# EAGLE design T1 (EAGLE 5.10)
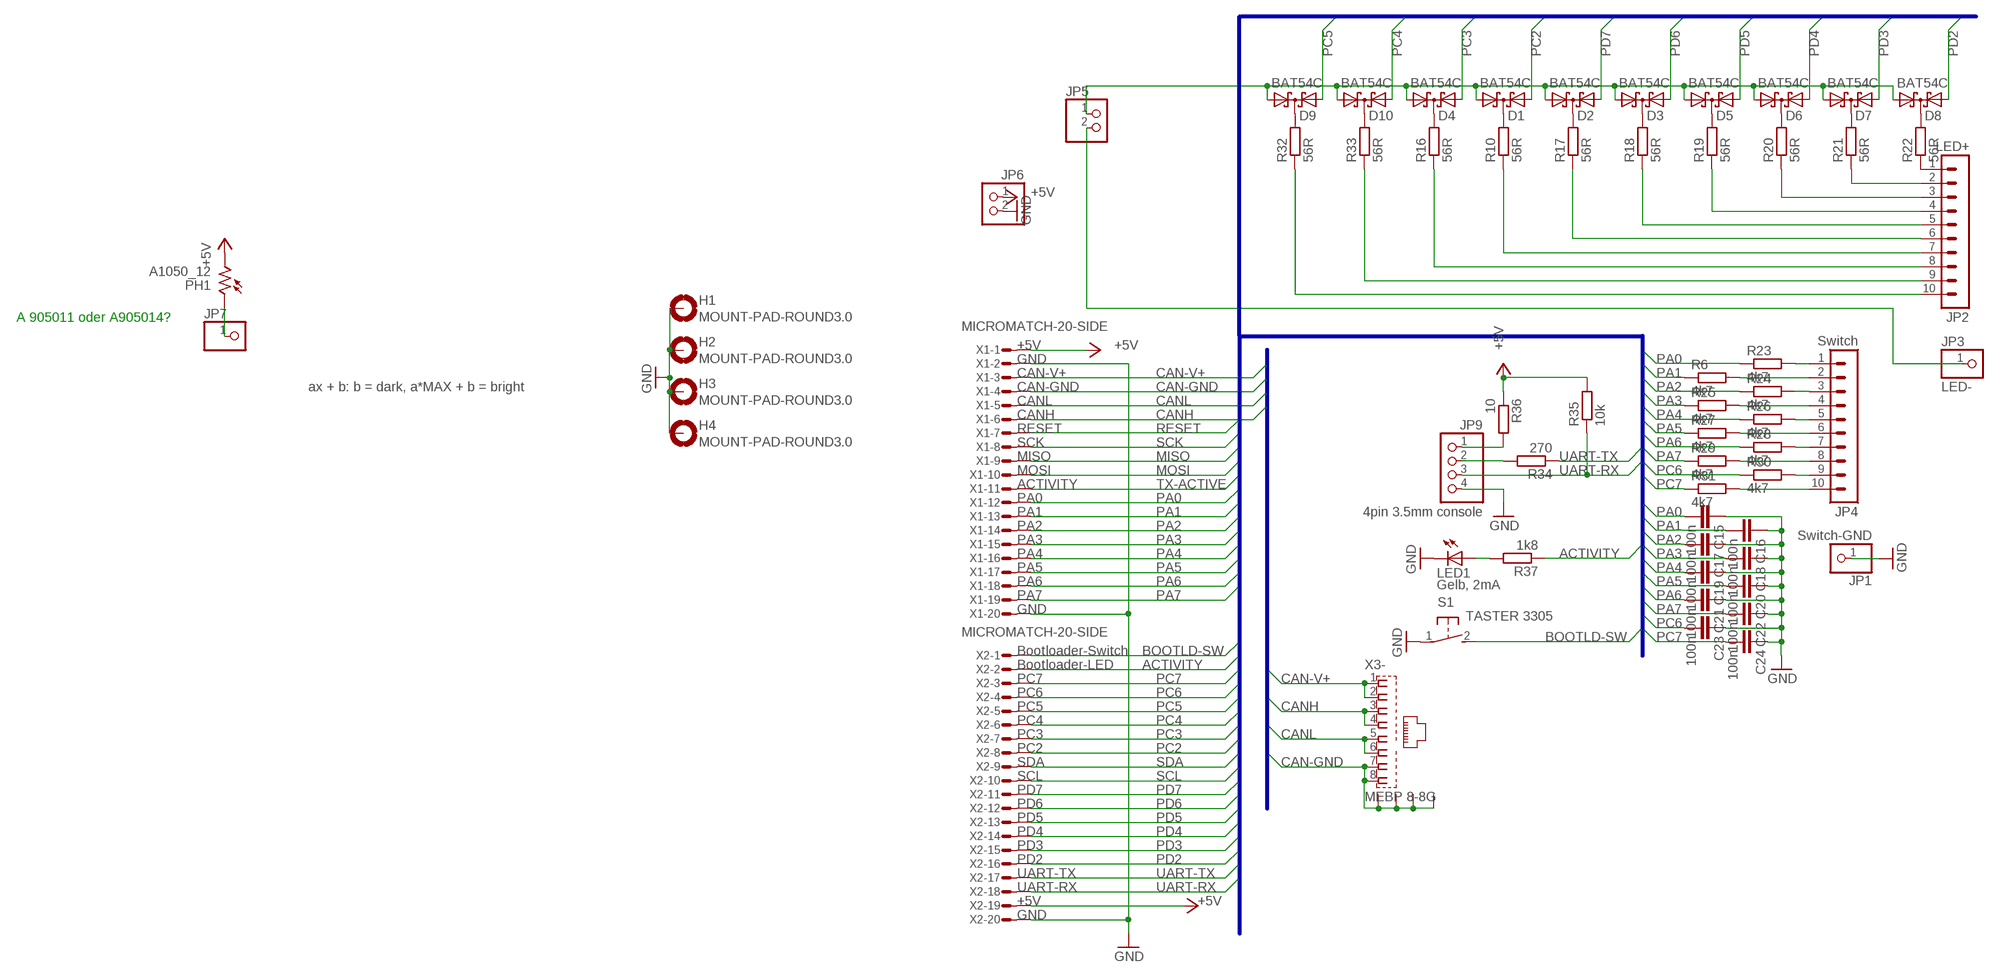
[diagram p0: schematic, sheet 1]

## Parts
C15  100n  C-EUC0805  [C0805]
C16  100n  C-EUC0805  [C0805]
C17  100n  C-EUC0805  [C0805]
C18  100n  C-EUC0805  [C0805]
C19  100n  C-EUC0805  [C0805]
C20  100n  C-EUC0805  [C0805]
C21  100n  C-EUC0805  [C0805]
C22  100n  C-EUC0805  [C0805]
C23  100n  C-EUC0805  [C0805]
C24  100n  C-EUC0805  [C0805]
D1  BAT54C  [SOT23]
D2  BAT54C  [SOT23]
D3  BAT54C  [SOT23]
D4  BAT54C  [SOT23]
D5  BAT54C  [SOT23]
D6  BAT54C  [SOT23]
D7  BAT54C  [SOT23]
D8  BAT54C  [SOT23]
D9  BAT54C  [SOT23]
D10  BAT54C  [SOT23]
H1  MOUNT-PAD-ROUND3.0  [3,0-PAD]
H2  MOUNT-PAD-ROUND3.0  [3,0-PAD]
H3  MOUNT-PAD-ROUND3.0  [3,0-PAD]
H4  MOUNT-PAD-ROUND3.0  [3,0-PAD]
JP1  Switch-GND  PINHD-1X1  [1X01]
JP2  LED+  MA10-1  [MA10-1]
JP3  LED-  PINHD-1X1  [1X01]
JP4  Switch  MA10-1  [MA10-1]
JP5  PINHD-1X2  [1X02]
JP6  PINHD-1X2  [1X02]
JP7  PINHD-1X1  [1X01]
JP9  4pin 3.5mm console  PINHD-1X4  [1X04]
LED1  Gelb, 2mA  LED3MM  [LED3MM]
PH1  A1050_12  [T0-46-A10XX]
R6  4k7  R-EU_0207/10  [0207/10]
R10  56R  R-EU_0207/10  [0207/10]
R16  56R  R-EU_0207/10  [0207/10]
R17  56R  R-EU_0207/10  [0207/10]
R18  56R  R-EU_0207/10  [0207/10]
R19  56R  R-EU_0207/10  [0207/10]
R20  56R  R-EU_0207/10  [0207/10]
R21  56R  R-EU_0207/10  [0207/10]
R22  56R  R-EU_0207/10  [0207/10]
R23  4k7  R-EU_0207/10  [0207/10]
R24  4k7  R-EU_0207/10  [0207/10]
R25  4k7  R-EU_0207/10  [0207/10]
R26  4k7  R-EU_0207/10  [0207/10]
R27  4k7  R-EU_0207/10  [0207/10]
R28  4k7  R-EU_0207/10  [0207/10]
R29  4k7  R-EU_0207/10  [0207/10]
R30  4k7  R-EU_0207/10  [0207/10]
R31  4k7  R-EU_0207/10  [0207/10]
R32  56R  R-EU_0207/10  [0207/10]
R33  56R  R-EU_0207/10  [0207/10]
R34  270  R-EU_R0805  [R0805]
R35  10k  R-EU_R0805  [R0805]
R36  10  R-EU_R0805  [R0805]
R37  1k8  R-EU_R0805  [R0805]
S1  TASTER 3305  31-XX  [B3F-31XX]
X1  MICROMATCH-20-SIDE  [MICROMATCH-20-SIDE]
X2  MICROMATCH-20-SIDE  [MICROMATCH-20-SIDE]
X3  MEBP 8-8G  RJ45  [RJ45]

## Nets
+5V: JP6.1 PH1.2 R35.2 R36.1 X1.1 X2.19
ACTIVITY: R37.1 X2.2
ACTIVITY_LED: LED1.A R37.2
BOOTLD-SW: S1.2(S) X2.1
CAN-GND [Power]: X1.4 X3.7 X3.8 X3.G1 X3.G2 X3.G3 X3.G4
CAN-V+ [Power]: X1.3 X3.1 X3.2
CANH: X1.6 X3.3 X3.4
CANL: X1.5 X3.5 X3.6
GND: C15.1 C16.1 C17.1 C18.1 C19.1 C20.1 C21.1 C22.1 C23.1 C24.1 H1.B3,0(MOUNT) H2.B3,0(MOUNT) H3.B3,0(MOUNT) H4.B3,0(MOUNT) JP1.1 JP6.2 JP9.4 LED1.K(C) S1.1(P) X1.2 X1.20 X2.20
MISO: X1.9
MOSI: X1.10
N$1: JP7.1 PH1.1
N$2: D4.3(CC) R16.2
N$14: JP4.1 R23.2
N$22: JP2.8 R16.1
N$23: D1.3(CC) R10.2
N$24: JP2.7 R10.1
N$25: JP4.3 R24.2
N$26: D2.3(CC) R17.2
N$27: JP2.6 R17.1
N$28: D3.3(CC) R18.2
N$29: JP2.5 R18.1
N$30: JP4.10 R31.2
N$31: D5.3(CC) R19.2
N$32: JP2.4 R19.1
N$33: D6.3(CC) R20.2
N$34: JP2.3 R20.1
N$35: JP4.2 R6.2
N$36: D7.3(CC) R21.2
N$37: JP2.2 R21.1
N$38: D8.3(CC) R22.2
N$39: JP2.1 R22.1
N$40: JP4.4 R25.2
N$41: JP4.5 R26.2
N$42: JP4.6 R27.2
N$43: JP4.7 R28.2
N$44: JP4.8 R29.2
N$45: JP4.9 R30.2
N$46: JP9.2 R34.2
N$47: JP9.1 R36.2
N$49: D9.3(CC) R32.2
N$50: JP2.10 R32.1
N$51: D10.3(CC) R33.2
N$52: JP2.9 R33.1
N$54: JP3.1 JP5.2
N$55: D1.1(A1) D2.1(A1) D3.1(A1) D4.1(A1) D5.1(A1) D6.1(A1) D7.1(A1) D8.1(A1) D9.1(A1) D10.1(A1) JP5.1
PA0: C15.2 R23.1 X1.12
PA1: C16.2 R6.1 X1.13
PA2: C17.2 R24.1 X1.14
PA3: C18.2 R25.1 X1.15
PA4: C19.2 R26.1 X1.16
PA5: C20.2 R27.1 X1.17
PA6: C21.2 R28.1 X1.18
PA7: C22.2 R29.1 X1.19
PC2: D1.2(A2) X2.8
PC3: D4.2(A2) X2.7
PC4: D10.2(A2) X2.6
PC5: D9.2(A2) X2.5
PC6: C23.2 R30.1 X2.4
PC7: C24.2 R31.1 X2.3
PD2: D8.2(A2) X2.16
PD3: D7.2(A2) X2.15
PD4: D6.2(A2) X2.14
PD5: D5.2(A2) X2.13
PD6: D3.2(A2) X2.12
PD7: D2.2(A2) X2.11
RESET: X1.7
SCK: X1.8
SCL: X2.10
SDA: X2.9
TX-ACTIVE: X1.11
UART-RX: JP9.3 R35.1 X2.18
UART-TX: R34.1 X2.17

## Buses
PA[0..7],PC[2..7],PD[2..7],SCK,MISO,MOSI,CAN-CS,BOOTLD-SW,CAN-INT,TX-ACTIVE,ACTIVITY,SDA,SCL,UART-RX,UART-TX,CLK,RESET
CANL,CANH,CAN-V+,CAN-GND

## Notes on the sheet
- A 905011 oder A905014?
- +5V
- GND
- CAN-V+
- ax + b: b = dark, a*MAX + b = bright | CAN-GND
- CANL
- CANH
- RESET
- SCK
- MISO
- MOSI
- ACTIVITY
- PA0
- PA1
- PA2
- PA3
- PA4
- PA5
- PA6
- PA7
- GND
- Bootloader-Switch
- Bootloader-LED
- PC7
- PC6
- PC5
- PC4
- PC3
- PC2
- SDA
- SCL
- PD7
- PD6
- PD5
- PD4
- PD3
- PD2
- UART-TX
- UART-RX
- +5V
- GND

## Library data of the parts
C15-C24 = rcl:C-EU: CAPACITOR, European symbol
D1-D10 = diode:BAT54C: Schottky Diodes Source: Fairchild .. BAT54.pdf
H1-H4 = holes:MOUNT-PAD-ROUND: MOUNTING PAD, round
JP1 JP3 JP7 = pinhead:PINHD-1X1: PIN HEADER
JP2 JP4 = con-lstb:MA10-1: PIN HEADER
JP5 JP6 = pinhead:PINHD-1X2: PIN HEADER
JP9 = pinhead:PINHD-1X4: PIN HEADER
LED1 = led:LED: LED
PH1 = photo-elements:A10: Sensor Robust Light Sensing Applications
R6 R10 R16-R37 = rcl:R-EU_: RESISTOR, European symbol
S1 = switch-omron:31-XX: OMRON SWITCH
X1 X2 = apbteam_con-amp-micromatch:MICROMATCH-20: Micro-MaTch 20 Straight connector: Suited for both, female and male.
X3 = con-appsys:RJ45: AMP connector

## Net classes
1 Power: width 0.5 mm

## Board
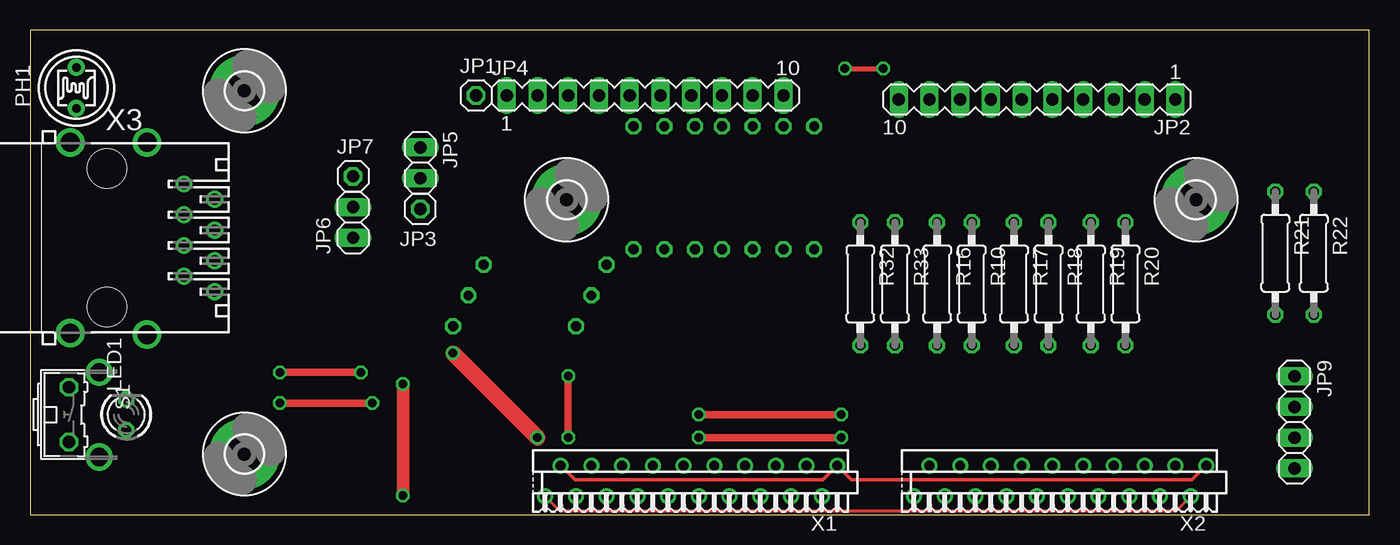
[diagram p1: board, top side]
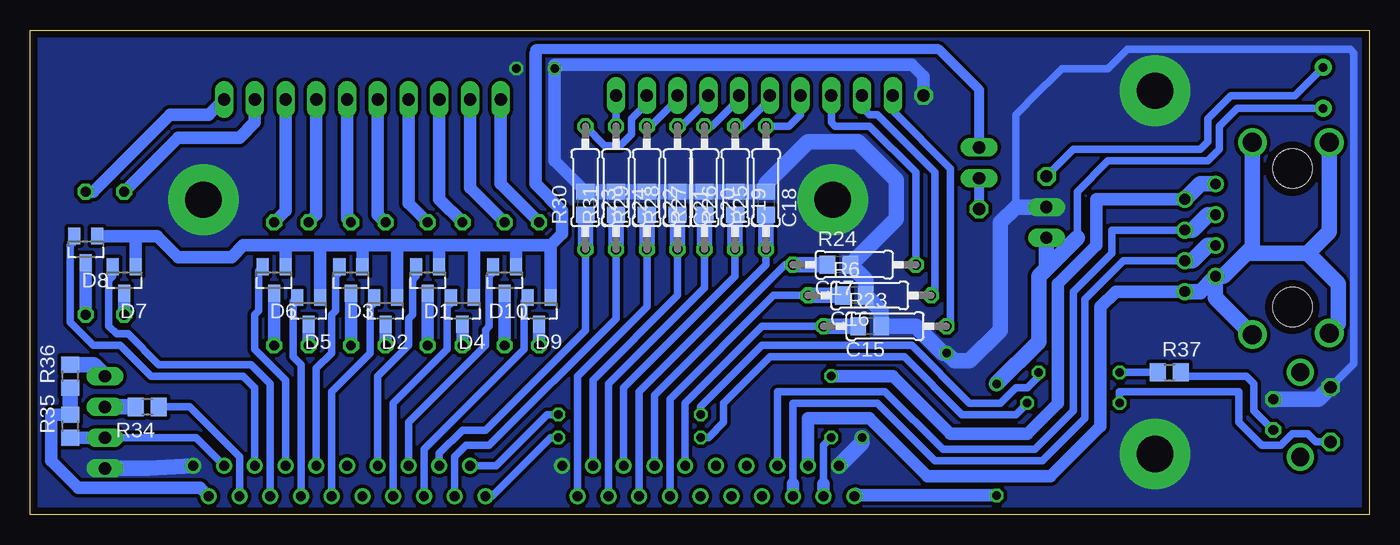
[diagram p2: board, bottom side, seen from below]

Size 110.63 x 40 mm. Coordinates in mm from the lower left corner, seen from the top.
Outline: 0,0 110.63,0 110.63,40 0,40 0,0
Copper layers (1*16): Top 0.035mm / dielectric 1.5mm / Bottom 0.035mm
Design rules "default *": minimum track width 10mil, minimum drill 24mil, track to track 0.3mm, track to pad 0.3mm, pad to pad 0.3mm, via to via 0.3mm, smd to smd 0.2mm, copper to edge 0.6mm, drill to drill 8mil, minimum pad ring 10mil, minimum via ring 8mil, stop-mask expansion 4mil, vias tented up to drill 0mil, thermal gap 10mil

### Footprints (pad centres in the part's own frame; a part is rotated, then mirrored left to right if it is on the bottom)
C0805 = smd 1.3 x 1.5: 1 -0.95,0; 2 0.95,0
SOT23 = smd 1 x 1.4: 1 -0.95,-1.1; 2 0.95,-1.1; 3 0,1.1
3,0-PAD = drill 3 pad 5.842 round: B3,0 0,0
1X01 = drill 1.016 octagon: 1 0,0
MA10-1 = drill 1.016 long: 1 -11.43,0; 2 -8.89,0; 3 -6.35,0; 4 -3.81,0; 5 -1.27,0; 6 1.27,0; 7 3.81,0; 8 6.35,0; 9 8.89,0; 10 11.43,0
1X02 = drill 1.016 long: 1 -1.27,0; 2 1.27,0
1X04 = drill 1.016 long: 1 -3.81,0; 2 -1.27,0; 3 1.27,0; 4 3.81,0
LED3MM = drill 0.813 octagon: A -1.27,0; K 1.27,0
T0-46-A10XX = drill 0.7 pad 1.4 round: 1 -1.7,0; 2 1.7,0
0207/10 = drill 0.813 octagon: 1 -5.08,0; 2 5.08,0
R0805 = smd 1.3 x 1.5: 1 -0.95,0; 2 0.95,0
B3F-31XX = drill 1.016 octagon: 1 -2.261,-1.245; 2 2.261,-1.245 | drill 1.499 pad 2.159 round: 3 -3.505,1.245; 4 3.505,1.245
MICROMATCH-20-SIDE = drill 0.813 round: 1 12.065,1.27; 2 10.795,-1.27; 3 9.525,1.27; 4 8.255,-1.27; 5 6.985,1.27; 6 5.715,-1.27; 7 4.445,1.27; 8 3.175,-1.27; 9 1.905,1.27; 10 0.635,-1.27; 11 -0.635,1.27; 12 -1.905,-1.27; 13 -3.175,1.27; 14 -4.445,-1.27; 15 -5.715,1.27; 16 -6.985,-1.27; 17 -8.255,1.27; 18 -9.525,-1.27; 19 -10.795,1.27; 20 -12.065,-1.27
RJ45 = drill 0.889 round: 1 -4.445,6.35; 2 -3.175,8.89; 3 -1.905,6.35; 4 -0.635,8.89; 5 0.635,6.35; 6 1.905,8.89; 7 3.175,6.35; 8 4.445,8.89 | drill 1.575 pad 2.184 round: G1 -7.874,-3.048; G2 7.874,-3.048; G3 -7.874,3.302; G4 8.001,3.302 | hole 3.251: -5.715,0; 5.715,0

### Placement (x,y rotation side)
C15  41.27,15.56 180 bottom
C16  42.55,18.1 180 bottom
C17  43.81,20.64 180 bottom
C18  49.85,25.72 270 bottom
C19  52.39,25.72 270 bottom
C20  54.93,25.72 270 bottom
C21  57.15,25.72 270 bottom
C22  59.69,25.72 270 bottom
C23  64.77,25.72 270 bottom
C24  62.23,25.72 270 bottom
D1  77.79,19.37 180 bottom
D2  81.28,16.83 180 bottom
D3  84.14,19.37 180 bottom
D4  74.93,16.83 180 bottom
D5  87.63,16.83 180 bottom
D6  90.49,19.37 180 bottom
D7  102.87,19.37 180 bottom
D8  106.05,21.91 180 bottom
D9  68.58,16.83 180 bottom
D10  71.44,19.37 180 bottom
H1  96.32,26 0 top
H2  44.32,26 0 top
H3  17.69,5 0 top
H4  17.69,35 0 top
JP1  36.83,34.61 0 top
JP2  83.19,34.29 180 top
JP3  32.23,25.24 180 top
JP4  50.8,34.61 0 top
JP5  32.23,29.05 270 top
JP6  26.67,24.13 90 top
JP7  26.67,27.94 0 top
JP9  104.46,7.62 270 top
LED1  7.94,8.26 90 top
PH1  3.81,35.24 270 top
R6  41.27,18.1 0 bottom
R10  77.79,19.05 270 top
R16  74.93,19.05 270 top
R17  81.28,19.05 270 top
R18  84.14,19.05 270 top
R19  87.63,19.05 270 top
R20  90.49,19.05 270 top
R21  102.87,21.59 270 top
R22  106.05,21.59 270 top
R23  40.01,15.56 0 bottom
R24  42.55,20.64 0 bottom
R25  49.85,26.99 90 bottom
R26  52.39,26.99 90 bottom
R27  54.93,26.99 90 bottom
R28  57.15,26.99 90 bottom
R29  59.69,26.99 90 bottom
R30  64.77,26.99 90 bottom
R31  62.23,26.99 90 bottom
R32  68.58,19.05 270 top
R33  71.44,19.05 270 top
R34  100.97,8.89 180 bottom
R35  107.31,7.3 90 bottom
R36  107.31,11.43 90 bottom
R37  16.51,11.75 0 bottom
S1  4.45,8.26 270 top
X1  54.61,2.77 180 top
X2  85.09,2.77 180 top
X3  6.35,22.86 270 top

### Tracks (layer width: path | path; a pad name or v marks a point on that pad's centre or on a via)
+5V  (via drill 0.7)
  Top 0.254: X1.1 43.73,0.32 94.7,0.32 X2.19
  Top 1.016: v30.8,1.59 v30.8,10.79
  Bottom 0.61: PH1.2 10.91,33.54 12.38,32.07 12.38,30.16 13.34,29.21 21.59,29.21 24.13,26.67 24.13,22.86
  Bottom 1.016: R35.2 108.9,8.25 108.9,8.26 108.9,4.45 106.68,2.22 96.61,2.22 X2.19 | v30.8,1.59 42.46,1.59
  Bottom 1.27: R35.2 R36.1 | 26.67,20.32 27.3,19.68 27.3,14.29 v30.8,10.79 | 26.67,20.32 24.13,22.86 | 42.46,1.59 X1.1 | 26.67,20.32 JP6.1
ACTIVITY  (via drill 0.7)
  Top 0.61: v20.64,11.75 v27.3,11.75 | v55.24,8.26 v66.99,8.26
  Bottom 0.61: R37.1 v20.64,11.75 | v27.3,11.75 27.3,11.43 28.26,10.48 29.21,10.48 30.48,9.21 33.02,9.21 37.78,13.97 50.16,13.97 55.24,8.89 v55.24,8.26 | v66.99,8.26 67.94,8.26 72.16,4.04 X2.2
ACTIVITY_LED
  Bottom 0.61: LED1.A 9.53,8.57 9.53,10.79 10.16,11.43 15.56,11.43 R37.2
BOOTLD-SW  (via drill 0.7)
  Top 0.61: v55.24,6.35 v66.99,6.35 | v20.64,9.21 v28.26,9.21
  Bottom 0.61: v66.99,6.35 67.63,6.35 72.48,1.5 X2.1 | S1.2 4.41,5.99 5.08,6.67 6.35,6.67 7.3,5.71 8.89,5.71 10.79,7.62 10.79,10.16 20.64,10.16 v20.64,9.21 | v28.26,9.21 29.21,8.26 33.66,8.26 38.42,13.02 49.53,13.02 53.34,9.21 53.34,7.62 54.61,6.35 v55.24,6.35
CAN-GND
  Bottom 1.016: X3.8 20.95,18.41 22.23,17.14 22.23,7.3 26.35,3.17 36.51,3.17 41.27,7.94 46.35,7.94 X1.4
  Bottom 1.27: X3.7 12.7,17.91 X3.G4 | X3.7 12.06,19.68 10.16,21.59 | 10.16,21.59 9.65,22.1 X3.G3 | X3.G2 2.54,15.75 2.54,19.05 5.08,21.59 | 5.08,21.59 10.16,21.59 | X3.G1 3.3,23.37 5.08,21.59 | X3.7 13.97,18.41 X3.8
CAN-V+  (via drill 0.7)
  Top 0.61: v44.45,11.43 v44.45,6.35
  Bottom 0.61: v44.45,6.35 45.09,5.71 45.09,2.54
  Bottom 1.016: X3.2 22.54,26.04 22.54,22.23 25.72,19.05 25.72,9.21 28.26,6.67 34.61,6.67 39.37,11.43 v44.45,11.43 | 45.09,2.54 X1.3
  Bottom 1.27: X3.1 13.97,27.3 X3.2
CANH
  Bottom 0.61: X3.4 21.27,23.5 21.27,21.59 24.45,18.41 24.45,8.57 27.62,5.4 35.24,5.4 40.01,10.16 48.9,10.16 X1.6
  Bottom 1.27: X3.3 13.34,24.77 14.61,23.5 X3.4
CANL
  Bottom 0.61: X3.6 20.32,20.95 23.5,17.78 23.5,7.94 26.99,4.45 35.88,4.45 40.64,9.21 47.62,9.21 47.62,2.54
  Bottom 1.016: 47.62,2.54 X1.5
  Bottom 1.27: X3.5 13.34,22.23 14.61,20.95 X3.6
GND  (via drill 0.7)
  Top 0.305: X2.20 95.97,2.86 67.86,2.86 X1.20 65.49,2.86 45,2.86 X1.2
  Top 0.406: v67.31,36.83 v70.48,36.83
  Top 1.27: v34.92,13.34 v41.91,6.35
  Bottom 0.61: S1.1 1.27,12.45 1.27,38.1 1.59,38.42 20,38.42 21.59,36.83 25.4,36.83 27.94,34.29 28.57,33.66 29.21,33.02 29.21,25.4
  Bottom 1.016: C23.1 67.31,29.21 v67.31,36.83 67.31,37.15 37.78,37.15 36.83,36.2 JP1.1
  Bottom 1.27: LED1.K 4.19,9.53 S1.1 | X1.2 41.91,5.95 v41.91,6.35 | C23.1 C24.1 C22.1 C21.1 C20.1 C19.1 C18.1 49.85,27.3 46.35,30.8 42.23,30.8 39.05,27.62 39.05,24.45 C17.1 41.59,19.37 C16.1 40.33,16.83 C15.1 37.47,15.56 35.24,13.34 v34.92,13.34 34.29,12.7 33.02,12.7 30.48,15.24 30.48,24.13 29.21,25.4 JP6.2 | JP9.4 100.88,3.81 X2.20
  pour Bottom (isolate 0.3, rank 5, no thermals): 0,40 0,0 110.63,0 110.63,40
N$1
  Bottom 0.61: PH1.1 6.14,34.61 11.43,34.61 13.34,32.7 13.34,30.8 13.97,30.16 24.45,30.16 JP7.1
N$2
  Bottom 1.016: R16.2 D4.3
N$14
  Bottom 0.61: JP4.1 39.37,33.34 34.61,28.57 34.61,15.88 R23.2
N$22
  Bottom 1.016: R16.1 76.83,26.04 JP2.8
N$23
  Bottom 1.016: R10.2 D1.3
N$24
  Bottom 1.016: R10.1 79.38,25.72 JP2.7
N$25
  Bottom 0.61: R24.2 37.47,28.26 41.27,32.07 44.13,32.07 44.45,32.38 JP4.3
N$26
  Bottom 1.016: R17.2 D2.3
N$27
  Bottom 1.016: R17.1 81.92,24.77 JP2.6
N$28
  Bottom 1.016: R18.2 D3.3
N$29
  Bottom 1.016: R18.1 84.45,24.45 JP2.5
N$30
  Bottom 0.61: R31.2 JP4.10
N$31
  Bottom 1.016: R19.2 D5.3
N$32
  Bottom 1.016: R19.1 87,24.77 JP2.4
N$33
  Bottom 1.016: R20.2 D6.3
N$34
  Bottom 1.016: R20.1 89.53,25.08 JP2.3
N$35
  Bottom 0.61: 41.91,34.29 JP4.2 41.91,33.66 41.27,33.02 40.64,33.02 35.88,28.26 35.88,18.41 R6.2
N$36
  Bottom 1.016: R21.2 D7.3
N$37
  Bottom 1.016: JP2.2 92.08,32.38 93.34,31.11 98.42,31.11 R21.1
N$38
  Bottom 1.016: D8.3 R22.2 106.05,18.76
N$39
  Bottom 1.016: JP2.1 95.89,33.02 99.06,33.02 105.41,26.67 R22.1
N$40
  Bottom 0.61: R25.2 47.94,32.07 46.99,33.02 JP4.4
N$41
  Bottom 0.61: R26.2 51.75,32.07 49.53,34.29 JP4.5
N$42
  Bottom 0.61: R27.2 54.29,32.07 52.07,34.29 JP4.6
N$43
  Bottom 0.61: R28.2 56.83,32.07 54.61,34.29 JP4.7
N$44
  Bottom 0.61: R29.2 59.37,32.07 57.15,34.29 JP4.8
N$45
  Bottom 0.61: R30.2 63.18,30.48 61.91,30.48 60.96,31.43 60.96,32.7 59.69,33.97 JP4.9
N$46
  Bottom 1.27: R34.2 JP9.2
N$47
  Bottom 1.27: JP9.1 105.41,12.38 R36.2
N$49
  Bottom 1.016: R32.2 D9.3
N$50
  Bottom 1.016: R32.1 71.75,27.3 JP2.10
N$51
  Bottom 1.016: R33.2 D10.3
N$52
  Bottom 1.016: R33.1 74.3,26.99 JP2.9
N$54
  Bottom 0.813: JP3.1 JP5.2
N$55
  Bottom 0.813: 68.9,38.1 68.9,38.42 35.56,38.42 32.23,35.08 JP5.1
  Bottom 1.016: 76.84,22.23 D1.1 | 89.54,22.23 D6.1 | D4.1 73.98,21.91 73.66,22.23 | 70.49,22.23 D10.1 | 70.49,22.23 73.66,22.23 | 67.63,22.23 D9.1 | 67.63,22.23 70.49,22.23 | 68.9,38.1 68.9,27.3 66.67,25.08 66.67,23.18 67.63,22.23 | 73.66,22.23 76.83,22.23 76.84,22.23 | 76.84,22.23 80.33,22.23 | 80.33,22.23 D2.1 | 80.33,22.23 83.19,22.23 | 83.19,22.23 D3.1 | 86.68,22.23 89.54,22.23 | 86.68,22.23 D5.1 | 83.19,22.23 86.68,22.23 | 89.54,22.23 93.03,22.23 93.98,21.27 98.42,21.27 100.16,23.01 101.6,23.01 | 101.6,23.01 D8.1 | D7.1 101.92,22.69 101.6,23.01
PA0
  Bottom 0.61: X1.12 56.52,9.21 50.16,15.56 R23.1
  Bottom 1.27: C15.2 R23.1
PA1
  Bottom 0.61: X1.13 57.78,9.53 49.21,18.1 R6.1
  Bottom 1.27: R6.1 C16.2
PA2
  Bottom 0.61: X1.14 59.05,9.84 48.26,20.64 R24.1
  Bottom 1.27: R24.1 C17.2
PA3
  Bottom 0.61: X1.15 60.33,10.16 49.85,20.64 R25.1
  Bottom 1.27: R25.1 C18.2
PA4
  Bottom 0.61: X1.16 61.59,10.48 52.39,19.68 R26.1
  Bottom 1.27: R26.1 C19.2
PA5
  Bottom 0.61: X1.17 62.87,10.79 54.93,18.73 R27.1
  Bottom 1.27: R27.1 C20.2
PA6
  Bottom 0.61: X1.18 64.14,11.11 57.15,18.1 R28.1
  Bottom 1.27: R28.1 C21.2
PA7
  Bottom 0.61: X1.19 65.41,11.43 59.69,17.14 R29.1
  Bottom 1.27: R29.1 C22.2
PC2
  Bottom 0.61: D1.2 78.74,19.69 79.06,19.37 79.06,16.51 79.38,16.19 79.38,13.97 81.92,11.43 X2.8
PC3
  Bottom 0.61: D4.2 75.88,17.46 76.2,17.14 76.2,13.65 80.64,9.21 X2.7
PC4
  Bottom 0.61: D10.2 72.39,20 72.71,19.68 72.71,15.56 73.03,15.24 73.03,13.97 79.38,7.62 X2.6
PC5
  Bottom 0.61: D9.2 69.85,17.61 69.85,13.65 78.11,5.4 X2.5
PC6
  Bottom 0.61: R30.1 64.77,15.24 73.03,6.99 74.93,6.99 76.83,5.08 X2.4
  Bottom 1.27: R30.1 C23.2
PC7
  Bottom 0.61: X2.3 75.56,4.76 74.61,5.71 72.71,5.71 62.23,16.19 R31.1
  Bottom 1.27: R31.1 C24.2
PD2
  Bottom 0.61: D8.2 107,22.55 107.31,22.23 107.31,15.88 105.41,13.97 103.19,13.97 100.65,11.43 93.03,11.43 92.08,10.48 X2.16
PD3
  Bottom 0.61: X2.15 90.81,10.79 92.39,12.38 100.01,12.38 102.55,14.92 103.5,14.92 104.14,15.56 104.14,19.37 103.82,19.69 D7.2
PD4
  Bottom 0.61: D6.2 91.76,20.15 91.76,16.83 92.08,16.51 92.08,13.65 89.53,11.11 X2.14
PD5
  Bottom 0.61: X2.13 88.27,12.38 88.9,13.02 88.9,17.61 D5.2
PD6
  Bottom 0.61: D3.2 85.09,20 85.41,19.68 85.41,16.83 85.72,16.51 85.72,13.34 87,12.06 X2.12
PD7
  Bottom 0.61: D2.2 82.23,17.46 82.55,17.14 82.55,13.34 85.72,10.16 X2.11
UART-RX
  Bottom 0.61: X2.18 96.92,6.35 JP9.3
  Bottom 1.016: JP9.3 R35.1
  Bottom 1.27: R35.1
UART-TX
  Bottom 0.61: X2.17 93.34,4.76 97.47,8.89 R34.1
